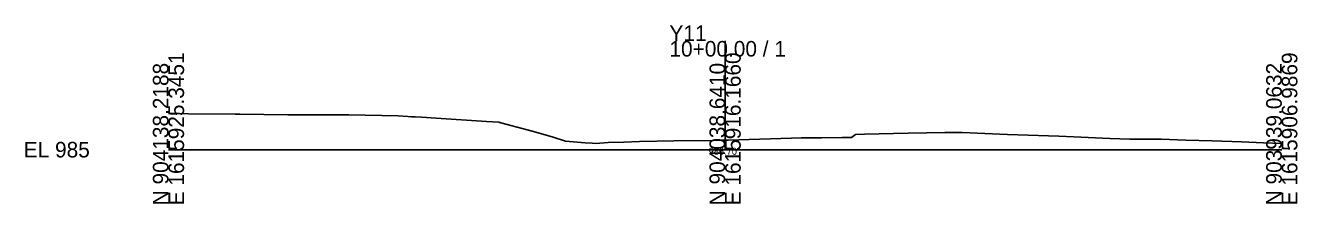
# Model space of a CAD drawing. Extents: x -26 to 203, y -10 to 2019.
# Drawn here: x -25.7 to 202.8, y -9.7 to 22.3 of the extents above; entities that cross this region are included whole.
import ezdxf

# ---------------------------------------------------------------- set-up
doc = ezdxf.new("R2010")
doc.units = 0
for name, color, linetype in [('Exist Cross Section Cell', 7, 'Continuous'), ('Exist XS Center Line Elevation Label', 7, 'Continuous'), ('Exist XS Ground Line', 7, 'Continuous')]:
    doc.layers.add(name, color=color, linetype=linetype)

msp = doc.modelspace()

# ---------------------------------------------------------------- linework, layer by layer
at = {"layer": 'Exist Cross Section Cell'}
for p, q in [((100, 0), (100, 19.54)), ((0, 0), (100, 0)), ((100, 0), (200, 0))]:
    msp.add_line(p, q, dxfattribs=at)
at = {"layer": 'Exist XS Ground Line'}
for p, q in [((0, 6.51), (1.97, 6.5)), ((1.97, 6.5), (3.61, 6.47)), ((3.61, 6.47), (12.01, 6.4)), ((12.01, 6.4), (12.8, 6.4)), ((12.8, 6.4), (21.43, 6.27)), ((21.43, 6.27), (22.07, 6.25)), ((22.07, 6.25), (31.52, 6.29)), ((31.52, 6.29), (32.43, 6.28)), ((32.43, 6.28), (41.28, 6.06)), ((41.28, 6.06), (43.02, 5.98)), ((43.02, 5.98), (43.65, 5.92)), ((43.65, 5.92), (44.3, 5.89)), ((44.3, 5.89), (45.47, 5.82)), ((45.47, 5.82), (48.07, 5.64)), ((48.07, 5.64), (57.12, 5.08)), ((57.12, 5.08), (59.36, 4.94)), ((59.36, 4.94), (59.72, 4.84)), ((59.72, 4.84), (65.6, 3.27)), ((65.6, 3.27), (69.11, 2.22)), ((122.71, 2.21), (123.43, 2.75)), ((123.43, 2.75), (125.06, 2.79)), ((125.06, 2.79), (132.91, 2.94)), ((132.91, 2.94), (139.46, 3.07)), ((139.46, 3.07), (142.57, 3.1)), ((142.57, 3.1), (150.73, 2.7)), ((150.73, 2.7), (152.61, 2.67)), ((152.61, 2.67), (159.93, 2.44)), ((159.93, 2.44), (162.65, 2.33)), ((162.65, 2.33), (169.12, 2.01)), ((69.11, 2.22), (71.32, 1.54)), ((71.32, 1.54), (74.87, 1.24)), ((74.87, 1.24), (76.11, 1.17)), ((76.11, 1.17), (76.73, 1.13)), ((76.73, 1.13), (78.29, 1.23)), ((78.29, 1.23), (78.97, 1.27)), ((78.97, 1.27), (81.82, 1.36)), ((81.82, 1.36), (84.63, 1.44)), ((84.63, 1.44), (90.77, 1.58)), ((90.77, 1.58), (97.9, 1.65)), ((97.9, 1.65), (99.22, 1.68)), ((99.22, 1.68), (100, 1.7)), ((100, 1.7), (100.56, 1.72)), ((100.56, 1.72), (111.91, 2.07)), ((111.91, 2.07), (113.67, 2.12)), ((113.67, 2.12), (115.01, 2.12)), ((115.01, 2.12), (115.31, 2.13)), ((115.31, 2.13), (117.3, 2.15)), ((117.3, 2.15), (121.02, 2.19)), ((121.02, 2.19), (122.71, 2.21)), ((169.12, 2.01), (172.7, 1.9)), ((172.7, 1.9), (178.32, 1.9)), ((178.32, 1.9), (182.74, 1.69)), ((182.74, 1.69), (187.51, 1.57)), ((187.51, 1.57), (192.78, 1.43)), ((192.78, 1.43), (196.71, 1.24)), ((196.71, 1.24), (200, 1.11))]:
    msp.add_line(p, q, dxfattribs=at)

# ---------------------------------------------------------------- texts
at = {"layer": 'Exist Cross Section Cell'}
for s, p in [('Y11', (90, 19.54)), ('10+00.00 / 1', (90, 16.74)), ('EL 985', (-26, -1.4))]:
    msp.add_text(s, height=2.8, dxfattribs=at).set_placement(p)
for s, p in [('E 1615925.3451', (2.8, -10)), ('E 1615916.1660', (102.8, -10)), ('E 1615906.9869', (202.8, -10)), ('N 904138.2188', (0, -10)), ('N 904038.6410', (100, -10)), ('N 903939.0632', (200, -10))]:
    msp.add_text(s, height=2.8, rotation=90, dxfattribs=at).set_placement(p)
at = {"layer": 'Exist XS Center Line Elevation Label'}
msp.add_text('986.70', height=1.25, dxfattribs=at).set_placement((97.02, -0.92))

doc.saveas('drawing.dxf')
